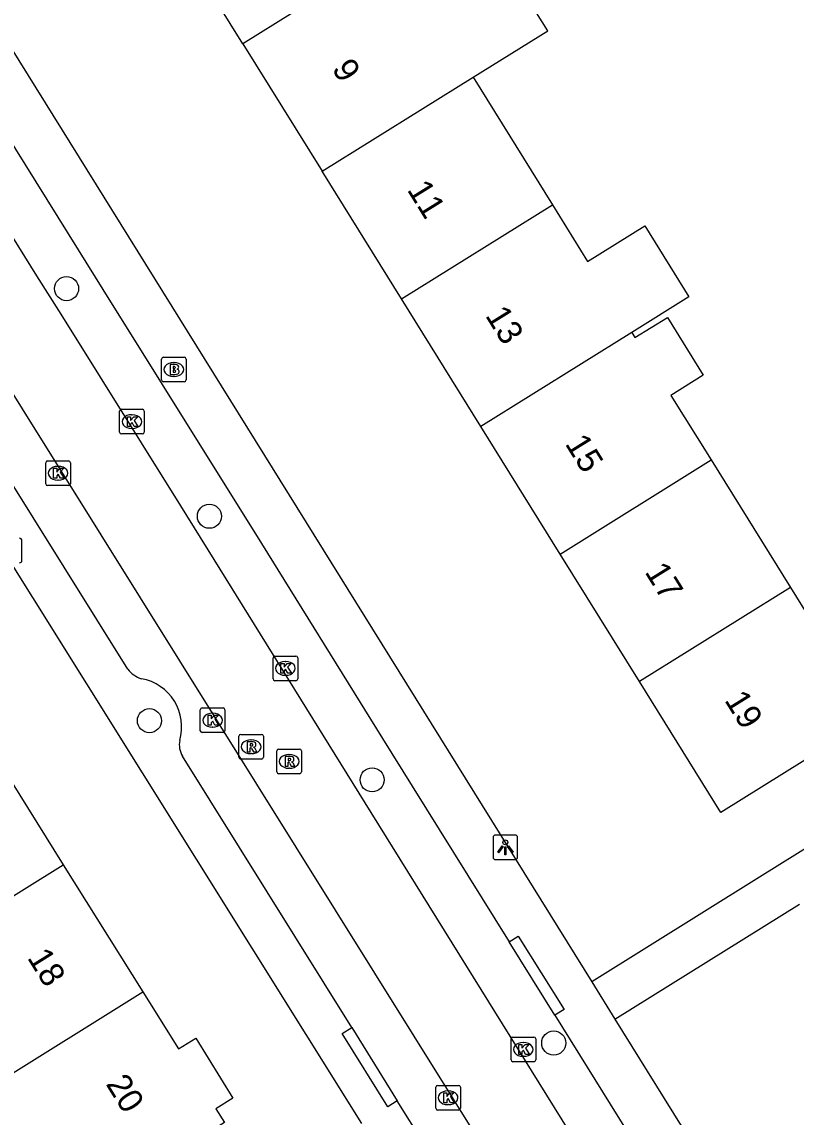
# Model space of a CAD drawing. Extents: x 159353 to 160616, y 385893 to 387321.
# Drawn here: x 159699.12 to 159730.58, y 386108.87 to 386153.33 of the extents above; entities that cross this region are included whole.
import ezdxf

# ---------------------------------------------------------------- set-up
doc = ezdxf.new("R2010")
doc.units = 0
for name, color, linetype in [('IMGEO_Boom', 7, 'Continuous'), ('IMGEO_Brandkraan', 7, 'Continuous'), ('IMGEO_Kolk', 7, 'Continuous'), ('IMGEO_Lichtpunt', 7, 'Continuous'), ('IMGEO_Pand', 7, 'Continuous'), ('IMGEO_Pand_nummerreeks', 7, 'Continuous'), ('IMGEO_Rijbaan_lokaal_open', 7, 'Continuous'), ('IMGEO_Rioolput', 7, 'Continuous'), ('IMGEO_Voetpad_open', 7, 'Continuous')]:
    doc.layers.add(name, color=color, linetype=linetype)

msp = doc.modelspace()

# ---------------------------------------------------------------- linework, layer by layer
at = {"layer": 'IMGEO_Boom'}
for centre in [(159700.938, 386142.499), (159706.741, 386133.259), (159704.305, 386124.96), (159713.353, 386122.558), (159720.73, 386111.874)]:
    msp.add_circle(centre, 0.489, dxfattribs=at)
at = {"layer": 'IMGEO_Brandkraan'}
for p, q in [((159704.871, 386139.716), (159705.723, 386139.716)), ((159704.796, 386138.79), (159704.796, 386139.642)), ((159705.284, 386139.496), (159705.309, 386139.496)), ((159705.797, 386139.642), (159705.797, 386138.79)), ((159705.307, 386138.936), (159705.282, 386138.936)), ((159705.723, 386138.716), (159704.871, 386138.716))]:
    msp.add_line(p, q, dxfattribs=at)
for points in [[(159704.871, 386139.716), (159705.723, 386139.716)], [(159704.796, 386138.79), (159704.796, 386139.642)], [(159705.144, 386139.416), (159705.144, 386139.016), (159705.357, 386139.016)], [(159705.375, 386139.416), (159705.144, 386139.416)], [(159705.323, 386139.335), (159705.269, 386139.335), (159705.269, 386139.259)], [(159705.797, 386139.642), (159705.797, 386138.79)], [(159705.269, 386139.259), (159705.322, 386139.259)], [(159705.331, 386139.183), (159705.269, 386139.183), (159705.269, 386139.102)], [(159705.269, 386139.102), (159705.331, 386139.102)], [(159705.723, 386138.716), (159704.871, 386138.716)]]:
    msp.add_lwpolyline(points, dxfattribs=at)
for centre, radius, start, end in [((159704.873, 386139.64), 0.0765, 91.552, 178.448), ((159704.873, 386139.64), 0.0765, 91.552, 178.448), ((159705.721, 386139.64), 0.0765, 1.552, 88.448), ((159705.721, 386139.64), 0.0765, 1.552, 88.448), ((159705.324, 386139.297), 0.0379, 267.8285, 90.9355), ((159705.379, 386139.271), 0.145, 59.4692, 91.5367), ((159705.404, 386139.318), 0.0922, 285.5137, 58.1501), ((159705.332, 386139.142), 0.0404, 269.8759, 90.5077), ((159705.363, 386139.267), 0.251, 268.6676, 293.5347), ((159705.409, 386139.126), 0.105, 301.3115, 78.989), ((159704.873, 386138.792), 0.0765, 181.552, 268.448), ((159704.873, 386138.792), 0.0765, 181.552, 268.448), ((159705.721, 386138.792), 0.0765, 271.552, 358.448), ((159705.721, 386138.792), 0.0765, 271.552, 358.448)]:
    msp.add_arc(centre, radius, start, end, dxfattribs=at)
for centre, major_axis, ratio, start_param, end_param in [((159705.283, 386139.216), (-0.387, 0.002), 0.722429, 4.712389, 7.853982), ((159705.308, 386139.216), (-0.39, 0.002), 0.717154, 1.570796, 4.712389)]:
    msp.add_ellipse(centre, major_axis=major_axis, ratio=ratio, start_param=start_param, end_param=end_param, dxfattribs=at)
at = {"layer": 'IMGEO_Kolk'}
for p, q in [((159703.094, 386136.673), (159703.094, 386137.525)), ((159703.169, 386137.599), (159704.021, 386137.599)), ((159704.095, 386137.525), (159704.095, 386136.673)), ((159703.582, 386137.379), (159703.607, 386137.379)), ((159703.605, 386136.819), (159703.58, 386136.819)), ((159704.021, 386136.599), (159703.169, 386136.599)), ((159700.093, 386134.578), (159700.093, 386135.43)), ((159700.168, 386135.504), (159701.02, 386135.504)), ((159700.581, 386135.284), (159700.606, 386135.284)), ((159701.094, 386135.43), (159701.094, 386134.578)), ((159701.02, 386134.504), (159700.168, 386134.504)), ((159700.604, 386134.724), (159700.579, 386134.724)), ((159709.329, 386126.657), (159709.329, 386127.509)), ((159709.404, 386127.583), (159710.256, 386127.583)), ((159709.817, 386127.363), (159709.842, 386127.363)), ((159710.33, 386127.509), (159710.33, 386126.657)), ((159710.256, 386126.583), (159709.404, 386126.583)), ((159709.84, 386126.803), (159709.815, 386126.803)), ((159706.37, 386124.553), (159706.37, 386125.405)), ((159706.445, 386125.479), (159707.297, 386125.479)), ((159706.858, 386125.259), (159706.883, 386125.259)), ((159707.371, 386125.405), (159707.371, 386124.553)), ((159706.881, 386124.699), (159706.856, 386124.699)), ((159707.297, 386124.479), (159706.445, 386124.479)), ((159718.996, 386111.188), (159718.996, 386112.04)), ((159719.071, 386112.114), (159719.923, 386112.114)), ((159719.484, 386111.894), (159719.509, 386111.894)), ((159719.997, 386112.04), (159719.997, 386111.188)), ((159719.507, 386111.334), (159719.482, 386111.334)), ((159719.923, 386111.114), (159719.071, 386111.114)), ((159715.939, 386109.226), (159715.939, 386110.078)), ((159716.014, 386110.152), (159716.866, 386110.152)), ((159716.427, 386109.932), (159716.452, 386109.932)), ((159716.94, 386110.078), (159716.94, 386109.226)), ((159716.866, 386109.152), (159716.014, 386109.152)), ((159716.45, 386109.372), (159716.425, 386109.372))]:
    msp.add_line(p, q, dxfattribs=at)
for points in [[(159703.094, 386136.673), (159703.094, 386137.525)], [(159703.169, 386137.599), (159704.021, 386137.599)], [(159704.095, 386137.525), (159704.095, 386136.673)], [(159703.415, 386137.299), (159703.538, 386137.299), (159703.538, 386137.148), (159703.668, 386137.299), (159703.832, 386137.299), (159703.686, 386137.148), (159703.839, 386136.899), (159703.687, 386136.899), (159703.602, 386137.063), (159703.538, 386136.996), (159703.538, 386136.899), (159703.415, 386136.899), (159703.415, 386137.299)], [(159704.021, 386136.599), (159703.169, 386136.599)], [(159700.093, 386134.578), (159700.093, 386135.43)], [(159700.168, 386135.504), (159701.02, 386135.504)], [(159701.094, 386135.43), (159701.094, 386134.578)], [(159700.414, 386135.204), (159700.537, 386135.204), (159700.537, 386135.053), (159700.667, 386135.204), (159700.831, 386135.204), (159700.685, 386135.053), (159700.838, 386134.804), (159700.686, 386134.804), (159700.601, 386134.968), (159700.537, 386134.901), (159700.537, 386134.804), (159700.414, 386134.804), (159700.414, 386135.204)], [(159701.02, 386134.504), (159700.168, 386134.504)], [(159709.329, 386126.657), (159709.329, 386127.509)], [(159709.404, 386127.583), (159710.256, 386127.583)], [(159709.65, 386127.283), (159709.773, 386127.283), (159709.773, 386127.132), (159709.903, 386127.283), (159710.067, 386127.283), (159709.921, 386127.132), (159710.074, 386126.883), (159709.922, 386126.883), (159709.837, 386127.047), (159709.773, 386126.98), (159709.773, 386126.883), (159709.65, 386126.883), (159709.65, 386127.283)], [(159710.33, 386127.509), (159710.33, 386126.657)], [(159710.256, 386126.583), (159709.404, 386126.583)], [(159706.37, 386124.553), (159706.37, 386125.405)], [(159706.445, 386125.479), (159707.297, 386125.479)], [(159706.691, 386125.179), (159706.814, 386125.179), (159706.814, 386125.028), (159706.944, 386125.179), (159707.108, 386125.179), (159706.962, 386125.028), (159707.115, 386124.779), (159706.963, 386124.779), (159706.878, 386124.943), (159706.814, 386124.876), (159706.814, 386124.779), (159706.691, 386124.779), (159706.691, 386125.179)], [(159707.371, 386125.405), (159707.371, 386124.553)], [(159707.297, 386124.479), (159706.445, 386124.479)], [(159718.996, 386111.188), (159718.996, 386112.04)], [(159719.071, 386112.114), (159719.923, 386112.114)], [(159719.317, 386111.814), (159719.44, 386111.814), (159719.44, 386111.663), (159719.57, 386111.814), (159719.734, 386111.814), (159719.588, 386111.663), (159719.741, 386111.414), (159719.589, 386111.414), (159719.504, 386111.578), (159719.44, 386111.511), (159719.44, 386111.414), (159719.317, 386111.414), (159719.317, 386111.814)], [(159719.997, 386112.04), (159719.997, 386111.188)], [(159719.923, 386111.114), (159719.071, 386111.114)], [(159715.939, 386109.226), (159715.939, 386110.078)], [(159716.014, 386110.152), (159716.866, 386110.152)], [(159716.94, 386110.078), (159716.94, 386109.226)], [(159716.26, 386109.852), (159716.383, 386109.852), (159716.383, 386109.701), (159716.513, 386109.852), (159716.677, 386109.852), (159716.531, 386109.701), (159716.684, 386109.452), (159716.532, 386109.452), (159716.447, 386109.616), (159716.383, 386109.549), (159716.383, 386109.452), (159716.26, 386109.452), (159716.26, 386109.852)], [(159716.866, 386109.152), (159716.014, 386109.152)]]:
    msp.add_lwpolyline(points, dxfattribs=at)
for centre, start, end in [((159703.171, 386137.523), 91.552, 178.448), ((159703.171, 386137.523), 91.552, 178.448), ((159704.019, 386137.523), 1.552, 88.448), ((159704.019, 386137.523), 1.552, 88.448), ((159703.171, 386136.675), 181.552, 268.448), ((159703.171, 386136.675), 181.552, 268.448), ((159704.019, 386136.675), 271.552, 358.448), ((159704.019, 386136.675), 271.552, 358.448), ((159700.17, 386135.428), 91.552, 178.448), ((159700.17, 386135.428), 91.552, 178.448), ((159701.018, 386135.428), 1.552, 88.448), ((159701.018, 386135.428), 1.552, 88.448), ((159700.17, 386134.58), 181.552, 268.448), ((159700.17, 386134.58), 181.552, 268.448), ((159701.018, 386134.58), 271.552, 358.448), ((159701.018, 386134.58), 271.552, 358.448), ((159709.406, 386127.507), 91.552, 178.448), ((159709.406, 386127.507), 91.552, 178.448), ((159710.254, 386127.507), 1.552, 88.448), ((159710.254, 386127.507), 1.552, 88.448), ((159709.406, 386126.659), 181.552, 268.448), ((159709.406, 386126.659), 181.552, 268.448), ((159710.254, 386126.659), 271.552, 358.448), ((159710.254, 386126.659), 271.552, 358.448), ((159706.447, 386125.403), 91.552, 178.448), ((159706.447, 386125.403), 91.552, 178.448), ((159707.295, 386125.403), 1.552, 88.448), ((159707.295, 386125.403), 1.552, 88.448), ((159706.447, 386124.555), 181.552, 268.448), ((159706.447, 386124.555), 181.552, 268.448), ((159707.295, 386124.555), 271.552, 358.448), ((159707.295, 386124.555), 271.552, 358.448), ((159719.073, 386112.038), 91.552, 178.448), ((159719.073, 386112.038), 91.552, 178.448), ((159719.921, 386112.038), 1.552, 88.448), ((159719.921, 386112.038), 1.552, 88.448), ((159719.073, 386111.19), 181.552, 268.448), ((159719.073, 386111.19), 181.552, 268.448), ((159719.921, 386111.19), 271.552, 358.448), ((159719.921, 386111.19), 271.552, 358.448), ((159716.016, 386110.076), 91.552, 178.448), ((159716.016, 386110.076), 91.552, 178.448), ((159716.864, 386110.076), 1.552, 88.448), ((159716.864, 386110.076), 1.552, 88.448), ((159716.016, 386109.228), 181.552, 268.448), ((159716.016, 386109.228), 181.552, 268.448), ((159716.864, 386109.228), 271.552, 358.448), ((159716.864, 386109.228), 271.552, 358.448)]:
    msp.add_arc(centre, 0.0765, start, end, dxfattribs=at)
for centre, major_axis, ratio, start_param, end_param in [((159703.581, 386137.099), (-0.387, 0.002), 0.722429, 4.712389, 7.853982), ((159703.606, 386137.099), (-0.39, 0.002), 0.717154, 1.570796, 4.712389), ((159700.58, 386135.004), (-0.387, 0.002), 0.722429, 4.712389, 7.853982), ((159700.605, 386135.004), (-0.39, 0.002), 0.717154, 1.570796, 4.712389), ((159709.816, 386127.083), (-0.387, 0.002), 0.722429, 4.712389, 7.853982), ((159709.841, 386127.083), (-0.39, 0.002), 0.717154, 1.570796, 4.712389), ((159706.857, 386124.979), (-0.387, 0.002), 0.722429, 4.712389, 7.853982), ((159706.882, 386124.979), (-0.39, 0.002), 0.717154, 1.570796, 4.712389), ((159719.483, 386111.614), (-0.387, 0.002), 0.722429, 4.712389, 7.853982), ((159719.508, 386111.614), (-0.39, 0.002), 0.717154, 1.570796, 4.712389), ((159716.426, 386109.652), (-0.387, 0.002), 0.722429, 4.712389, 7.853982), ((159716.451, 386109.652), (-0.39, 0.002), 0.717154, 1.570796, 4.712389)]:
    msp.add_ellipse(centre, major_axis=major_axis, ratio=ratio, start_param=start_param, end_param=end_param, dxfattribs=at)
at = {"layer": 'IMGEO_Lichtpunt'}
for p, q in [((159699.123, 386131.462), (159699.123, 386132.269)), ((159699.123, 386131.462), (159699.123, 386132.269)), ((159718.267, 386120.221), (159718.267, 386119.414)), ((159718.267, 386120.221), (159718.267, 386119.414)), ((159719.169, 386120.316), (159718.361, 386120.316)), ((159719.169, 386120.316), (159718.361, 386120.316)), ((159719.263, 386119.414), (159719.263, 386120.221)), ((159719.263, 386119.414), (159719.263, 386120.221)), ((159718.361, 386119.32), (159719.169, 386119.32)), ((159718.361, 386119.32), (159719.169, 386119.32))]:
    msp.add_line(p, q, dxfattribs=at)
for points in [[(159718.641, 386119.885), (159718.68, 386119.857), (159718.492, 386119.595), (159718.454, 386119.622), (159718.641, 386119.885)], [(159718.743, 386119.837), (159718.79, 386119.837), (159718.79, 386119.515), (159718.743, 386119.515), (159718.743, 386119.837)], [(159718.853, 386119.857), (159718.891, 386119.884), (159719.078, 386119.622), (159719.039, 386119.594), (159718.853, 386119.857)]]:
    msp.add_lwpolyline(points, dxfattribs=at)
msp.add_circle((159718.766, 386120.019), 0.0994, dxfattribs=at)
for centre, start, end in [((159699.029, 386132.269), 0, 90), ((159699.029, 386132.269), 0, 90), ((159699.029, 386131.462), 270, 0), ((159699.029, 386131.462), 270, 360), ((159718.361, 386120.221), 90, 180), ((159718.361, 386120.221), 90, 180), ((159719.169, 386120.221), 0, 90), ((159719.169, 386120.221), 0, 90), ((159718.361, 386119.414), 180, 270), ((159718.361, 386119.414), 180, 270), ((159719.169, 386119.414), 270, 0), ((159719.169, 386119.414), 270, 360)]:
    msp.add_arc(centre, 0.0946, start, end, dxfattribs=at)
at = {"layer": 'IMGEO_Pand'}
for points in [[(159708.095, 386152.441), (159704.872, 386157.62)], [(159717.46, 386151.087), (159720.485, 386152.968), (159719.504, 386154.545), (159719.276, 386154.403), (159718.78, 386154.627), (159718.826, 386155.061), (159718.837, 386155.626), (159718.704, 386156.203), (159718.327, 386156.824), (159717.774, 386157.324), (159716.439, 386157.635), (159714.231, 386156.262)], [(159714.231, 386156.262), (159708.095, 386152.441)], [(159708.095, 386152.441), (159711.318, 386147.263)], [(159711.318, 386147.263), (159717.46, 386151.087)], [(159717.46, 386151.087), (159720.677, 386145.904)], [(159714.541, 386142.083), (159711.318, 386147.263)], [(159714.541, 386142.083), (159720.677, 386145.904)], [(159720.677, 386145.904), (159722.108, 386143.604), (159724.427, 386145.049), (159726.218, 386142.17), (159723.9, 386140.724)], [(159717.764, 386136.904), (159714.541, 386142.083)], [(159723.9, 386140.724), (159724.032, 386140.512), (159725.347, 386141.329), (159726.807, 386138.981), (159725.493, 386138.164), (159727.122, 386135.545)], [(159723.9, 386140.724), (159717.764, 386136.904)], [(159720.986, 386131.725), (159717.764, 386136.904)], [(159720.986, 386131.725), (159727.122, 386135.545)], [(159727.122, 386135.545), (159730.345, 386130.367)], [(159724.209, 386126.546), (159720.986, 386131.725)], [(159730.345, 386130.367), (159733.651, 386125.054), (159731.76, 386123.877), (159727.514, 386121.235), (159724.209, 386126.546)], [(159730.345, 386130.367), (159724.209, 386126.546)], [(159697.577, 386124.257), (159700.802, 386119.114)], [(159694.668, 386115.298), (159700.802, 386119.114)], [(159700.802, 386119.114), (159704.041, 386113.948)], [(159697.892, 386110.122), (159704.041, 386113.948)], [(159704.041, 386113.948), (159705.491, 386111.635), (159706.188, 386112.069), (159707.7, 386109.641), (159707.002, 386109.206), (159707.35, 386108.646), (159705.102, 386107.246), (159706.688, 386104.7)]]:
    msp.add_lwpolyline(points, dxfattribs=at)
at = {"layer": 'IMGEO_Rijbaan_lokaal_open'}
for points in [[(159732.063, 386091.102), (159713.32, 386121.238), (159712.101, 386123.199), (159706.934, 386131.508), (159705.576, 386133.684), (159700.717, 386141.456), (159699.735, 386143.025), (159695.462, 386149.864), (159694.078, 386152.113), (159686.42, 386164.358)], [(159684.734, 386160.648), (159729.424, 386089.133)]]:
    msp.add_lwpolyline(points, dxfattribs=at)
at = {"layer": 'IMGEO_Rioolput'}
for p, q in [((159707.937, 386123.475), (159707.937, 386124.327)), ((159708.012, 386124.401), (159708.864, 386124.401)), ((159708.425, 386124.181), (159708.45, 386124.181)), ((159708.938, 386124.327), (159708.938, 386123.475)), ((159709.48, 386122.881), (159709.48, 386123.733)), ((159709.555, 386123.807), (159710.407, 386123.807)), ((159710.481, 386123.733), (159710.481, 386122.881)), ((159708.864, 386123.401), (159708.012, 386123.401)), ((159708.448, 386123.621), (159708.423, 386123.621)), ((159709.968, 386123.587), (159709.993, 386123.587)), ((159709.991, 386123.027), (159709.966, 386123.027)), ((159710.407, 386122.807), (159709.555, 386122.807))]:
    msp.add_line(p, q, dxfattribs=at)
for points in [[(159707.937, 386123.475), (159707.937, 386124.327)], [(159708.012, 386124.401), (159708.864, 386124.401)], [(159708.938, 386124.327), (159708.938, 386123.475)], [(159708.526, 386124.099), (159708.274, 386124.101), (159708.274, 386123.701)], [(159708.274, 386123.701), (159708.398, 386123.701), (159708.398, 386123.863), (159708.409, 386123.863)], [(159708.452, 386124.02), (159708.398, 386124.02), (159708.398, 386123.939)], [(159708.398, 386123.939), (159708.45, 386123.939)], [(159708.456, 386123.834), (159708.527, 386123.701), (159708.667, 386123.701), (159708.602, 386123.827)], [(159709.48, 386122.881), (159709.48, 386123.733)], [(159709.555, 386123.807), (159710.407, 386123.807)], [(159710.481, 386123.733), (159710.481, 386122.881)], [(159708.864, 386123.401), (159708.012, 386123.401)], [(159710.069, 386123.505), (159709.817, 386123.507), (159709.817, 386123.107)], [(159709.817, 386123.107), (159709.941, 386123.107), (159709.941, 386123.269), (159709.952, 386123.269)], [(159709.995, 386123.426), (159709.941, 386123.426), (159709.941, 386123.345)], [(159709.941, 386123.345), (159709.993, 386123.345)], [(159709.999, 386123.24), (159710.07, 386123.107), (159710.21, 386123.107), (159710.145, 386123.233)], [(159710.407, 386122.807), (159709.555, 386122.807)]]:
    msp.add_lwpolyline(points, dxfattribs=at)
for centre, radius, start, end in [((159708.014, 386124.325), 0.0765, 91.552, 178.448), ((159708.014, 386124.325), 0.0765, 91.552, 178.448), ((159708.862, 386124.325), 0.0765, 1.552, 88.448), ((159708.862, 386124.325), 0.0765, 1.552, 88.448), ((159708.408, 386123.81), 0.0533, 26.0293, 88.6989), ((159708.434, 386124.128), 0.19, 274.7715, 282.9687), ((159708.458, 386123.924), 0.0964, 77.0061, 93.1865), ((159708.472, 386123.981), 0.0378, 276.6634, 79.6772), ((159708.525, 386123.989), 0.109, 350.3612, 89.416), ((159708.523, 386123.989), 0.112, 277.5842, 350.9817), ((159708.507, 386123.774), 0.108, 29.5134, 73.7905), ((159709.557, 386123.731), 0.0765, 91.552, 178.448), ((159709.557, 386123.731), 0.0765, 91.552, 178.448), ((159710.405, 386123.731), 0.0765, 1.552, 88.448), ((159710.405, 386123.731), 0.0765, 1.552, 88.448), ((159708.014, 386123.477), 0.0765, 181.552, 268.448), ((159708.014, 386123.477), 0.0765, 181.552, 268.448), ((159708.862, 386123.477), 0.0765, 271.552, 358.448), ((159708.862, 386123.477), 0.0765, 271.552, 358.448), ((159709.951, 386123.216), 0.0533, 26.0293, 88.6989), ((159709.977, 386123.534), 0.19, 274.7715, 282.9687), ((159710.001, 386123.33), 0.0964, 77.0061, 93.1865), ((159710.015, 386123.387), 0.0378, 276.6634, 79.6772), ((159710.068, 386123.395), 0.109, 350.3612, 89.416), ((159710.066, 386123.395), 0.112, 277.5842, 350.9817), ((159710.05, 386123.18), 0.108, 29.5134, 73.7905), ((159709.557, 386122.883), 0.0765, 181.552, 268.448), ((159709.557, 386122.883), 0.0765, 181.552, 268.448), ((159710.405, 386122.883), 0.0765, 271.552, 358.448), ((159710.405, 386122.883), 0.0765, 271.552, 358.448)]:
    msp.add_arc(centre, radius, start, end, dxfattribs=at)
for centre, major_axis, ratio, start_param, end_param in [((159708.424, 386123.901), (-0.387, 0.002), 0.722429, 4.712389, 7.853982), ((159708.449, 386123.901), (-0.39, 0.002), 0.717154, 1.570796, 4.712389), ((159709.967, 386123.307), (-0.387, 0.002), 0.722429, 4.712389, 7.853982), ((159709.992, 386123.307), (-0.39, 0.002), 0.717154, 1.570796, 4.712389)]:
    msp.add_ellipse(centre, major_axis=major_axis, ratio=ratio, start_param=start_param, end_param=end_param, dxfattribs=at)
at = {"layer": 'IMGEO_Voetpad_open'}
for points in [[(159685.685, 386173.135), (159722.272, 386114.357)], [(159712.934, 386108.61), (159677.208, 386165.677), (159674.448, 386166.054)], [(159689.763, 386162.72), (159695.716, 386153.19), (159697.136, 386150.917), (159701.414, 386144.069), (159702.412, 386142.47), (159707.231, 386134.755), (159708.615, 386132.541), (159713.768, 386124.242), (159714.974, 386122.307), (159718.917, 386115.978)], [(159703.425, 386127.051), (159694.388, 386141.485)], [(159742.836, 386135.315), (159746.659, 386129.537), (159728.985, 386118.536), (159722.272, 386114.357)], [(159712.525, 386112.5), (159705.653, 386123.513)], [(159723.212, 386112.846), (159730.714, 386117.516)], [(159718.917, 386115.978), (159719.286, 386116.213), (159721.153, 386113.232), (159720.775, 386113.01)], [(159720.775, 386113.01), (159718.917, 386115.978)], [(159722.272, 386114.357), (159723.212, 386112.846)], [(159720.775, 386113.01), (159732.147, 386094.729)], [(159723.212, 386112.846), (159738.007, 386089.077)], [(159714.373, 386109.524), (159713.989, 386109.286), (159712.133, 386112.264), (159712.525, 386112.5)], [(159712.525, 386112.5), (159714.373, 386109.524)], [(159715.436, 386107.819), (159714.373, 386109.524)]]:
    msp.add_lwpolyline(points, dxfattribs=at)
for centre, radius, start, end in [((159704.345, 386127.777), 1.172, 218.2668, 252.2157), ((159703.627, 386124.706), 1.988, 343.9949, 79.5745), ((159706.395, 386123.978), 0.876, 168.1524, 212.0662)]:
    msp.add_arc(centre, radius, start, end, dxfattribs=at)

# ---------------------------------------------------------------- texts
at = {"layer": 'IMGEO_Pand_nummerreeks'}
for s, rotation, p in [('9', 301.8906, (159711.694, 386151.427)), ('11', 301.8931, (159714.75, 386146.516)), ('13', 301.8931, (159717.928, 386141.408)), ('15', 301.8906, (159721.167, 386136.202)), ('17', 301.8931, (159724.406, 386130.999)), ('19', 301.8931, (159727.645, 386125.794)), ('18', 301.9122, (159699.319, 386115.337)), ('20', 301.9135, (159702.511, 386110.211))]:
    msp.add_text(s, height=1, rotation=rotation, dxfattribs=at).set_placement(p)

doc.saveas('drawing.dxf')
